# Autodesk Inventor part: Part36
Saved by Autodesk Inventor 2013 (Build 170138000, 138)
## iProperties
Created: 2012-07
Part Number: Part36
Material: Acetal Resin, Black
Document SubType Name: Modeling
Designer: Paul
Density: 1 g/cm^3
Author: Paul
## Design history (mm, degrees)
node "User Library-Arduino Mega.SAT1"
body "Solid1"
node "Base1"
